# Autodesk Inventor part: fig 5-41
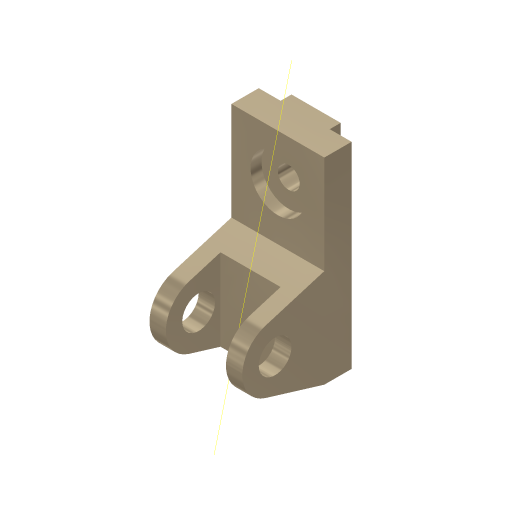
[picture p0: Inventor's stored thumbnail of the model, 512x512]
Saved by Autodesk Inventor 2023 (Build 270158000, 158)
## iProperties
Created: 2001-11
Part Number: fig 5-41
Document SubType Name: Modeling
Designer: Renu Muthoo
Density: 1 g/cm^3
Material: Generic
Appearance: Metal-Titanium (Polished)
Control State: 0
Master: False
Checked Out: False
Shininess: 65.0
Angle Display Precision: 2
Document Length Units: 11269
Document Angle Units: 11279
Document Time Units: 11290
Document Mass Units: 11283
Document Length Units Precision: 3
Document Angle Units Precision: 2
Density: 0.0
Volumn: 0.0
Area: 0.0
PropertySet Name: Model Information
Author: Renu Muthoo
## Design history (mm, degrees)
node "Sketch1"
sketch "Sketch2"
  geometry: L1 (33.257, 104.664)-(33.257, -75.336); L2 (33.257, -75.336)-(8.257, -75.336); L3 (8.257, -75.336)-(-45.451, -59.045); L4 (-45.451, -1.628)-(8.257, 14.664); L5 (8.257, 14.664)-(8.257, 104.664); L6 (8.257, 104.664)-(33.257, 104.664); C1 r 15 at (-36.743, -30.336); A1 r 30 centre (-36.743, -30.336) between (-45.451, -1.628) and (-45.451, -59.045)
  constraints: 12 end point, 2 centre point, 2 equal length, 2 parallel, 2 point on circle, 2 tangent, 1 coincident, 1 perpendicular, 1 vertical
  dimensions: "d0" = 180 distance of L1.start L1.end; "d1" = 30 radius of A1; "d2" = 25 distance of L5.end L1.start; "d3" = 45 distance from line of L2 A1.centre; "d4" = 70 distance from line of L1 A1.centre; "d5" = 30 diameter of C1
extrude "Extrusion1" new body sketch "Sketch2" distance "d6" = 85; taper "d7" = 0 deg
workplane "Work Plane1"
sketch "Sketch3"
  geometry: L1 (15, 62.364)-(70, 62.364); L2 (70, 62.364)-(70, -52.386); L3 (70, -52.386)-(15, -52.386); L4 (15, -52.386)-(15, 62.364); L5 (0, -45)-(0, -28.708) reference
  constraints: 8 end point, 2 parallel, 1 horizontal, 1 perpendicular
  dimensions: "d8" = 55 distance of L1.start L1.end; "d9" = 15 distance between parallel lines of L5 L4
extrude "Extrusion2" cut sketch "Sketch3" distance "d10" = 50; taper "d11" = 0 deg
sketch "Sketch4"
  geometry: L1 (0, 25)-(85, 25) reference; L2 (0, 0)-(0, 25) reference; L3 (20, 25)-(65, 25); L4 (65, 25)-(65, 35); L5 (65, 35)-(20, 35); L6 (20, 35)-(20, 25)
  constraints: 8 end point, 2 parallel, 1 horizontal, 1 perpendicular, 1 point on line
  dimensions: "d12" = 45 distance of L4.end L5.end; "d13" = 10 distance of L3.end L4.end; "d14" = 20 distance between parallel lines of L2 L6
extrude "Extrusion3" join sketch "Sketch4" stored distance "d15" = 50; taper "d16" = 0 deg
sketch "Sketch5"
  geometry: L1 (85, 0)-(85, 90) reference; L2 (0, 90)-(85, 90) reference; 1 further point
  dimensions: "d17" = 42 distance from line of L2 point (42.5, 48); "d18" = 42.5 distance from line of L1 point (42.5, 48)
hole "Hole1" sketch "Sketch5" at (42.5, 48) diameter "d19" = 20; stored, may be unused: countersink angle "d23" = 82 deg, drill point angle "d25" = 118 deg; dims "d20" = 6, "d21" = 50, "d22" = 10, "d24" = 8
workaxis "Work Axis1"
body "Solid1"
